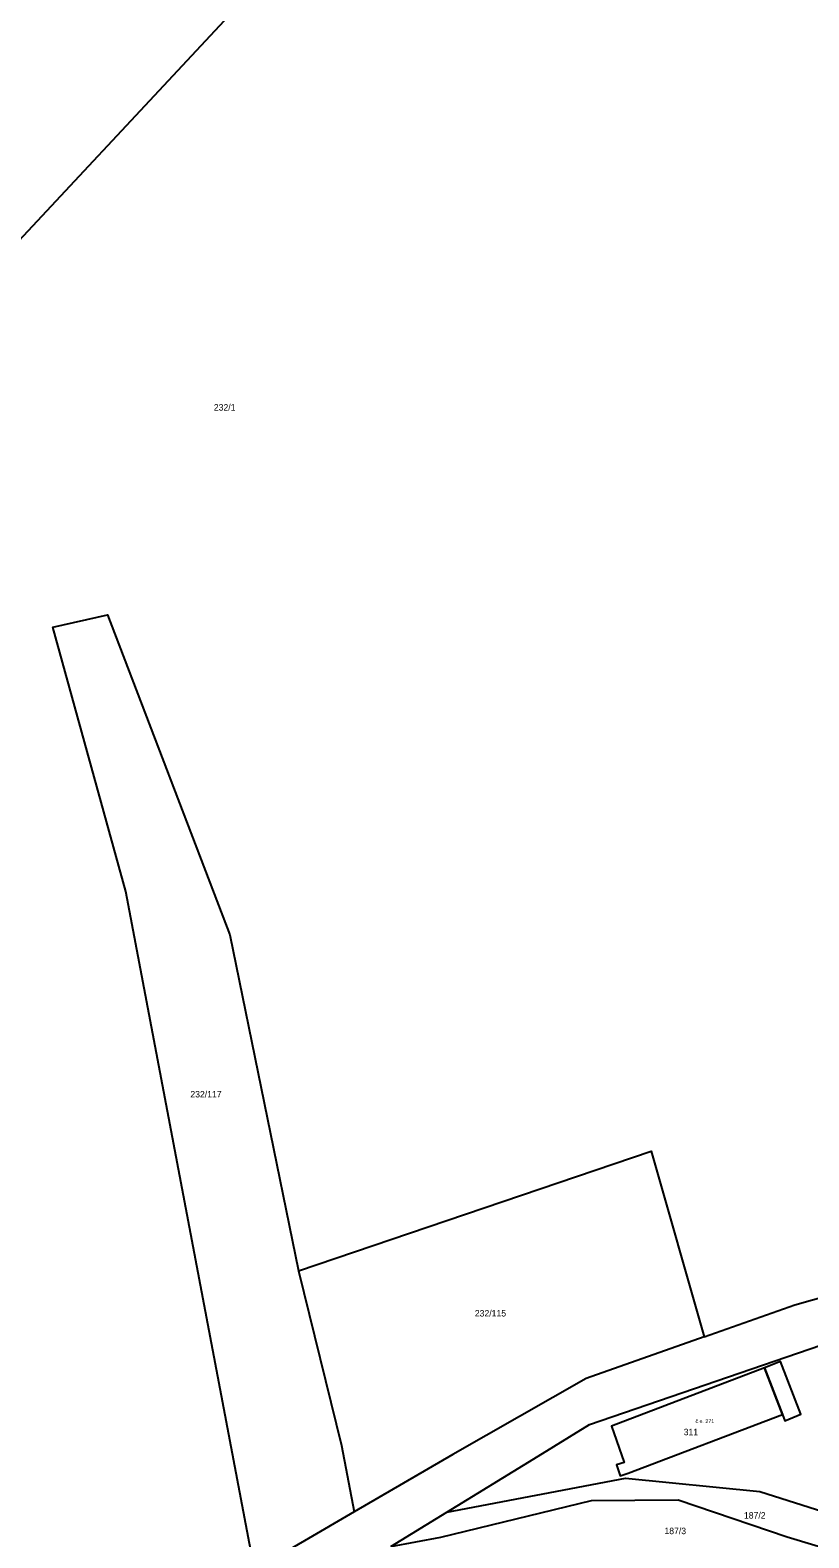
# Model space of a CAD drawing. Extents: x -887272 to -877616, y -1026687 to -1019819.
# Drawn here: x -882233.5 to -882028.8, y -1024011.9 to -1023615.5 of the extents above; entities that cross this region are included whole.
import ezdxf

# ---------------------------------------------------------------- set-up
doc = ezdxf.new("R2010")
doc.units = 0
for name, color, linetype in [('Definiční body', 7, 'Continuous'), ('Hranice parcel', 7, 'Continuous'), ('Parcelní čísla', 7, 'Continuous'), ('Polygon budovy', 7, 'Continuous'), ('Vnitřní kresba', 7, 'Continuous')]:
    doc.layers.add(name, color=color, linetype=linetype)

msp = doc.modelspace()

# ---------------------------------------------------------------- linework, layer by layer
at = {"layer": 'Hranice parcel'}
for p, q in [((-882123.98, -1024005.14), (-882101.11, -1023991.13)), ((-882138.72, -1024014.17), (-882123.98, -1024005.14))]:
    msp.add_line(p, q, dxfattribs=at)
for points in [[(-882058.02, -1023479.44), (-882103.84, -1023528.65), (-882178.79, -1023609.12), (-882251.38, -1023686.73), (-882326.67, -1023766.9), (-882416, -1023862), (-882806.28, -1023803.54), (-882785.58, -1023775.53)], [(-882174.49, -1024020.26), (-882208.33, -1023841.98), (-882227.5, -1023772.45), (-882213.17, -1023769.2), (-882180.99, -1023853.37), (-882162.93, -1023941.67)], [(-882162.93, -1023941.67), (-882070.28, -1023910.2), (-882056.31, -1023959.06)], [(-882162.93, -1023941.67), (-882151.68, -1023987.61), (-882148.29, -1024005.05)], [(-882056.31, -1023959.06), (-882032.46, -1023950.59), (-881999.39, -1023941.22)], [(-882101.11, -1023991.13), (-882086.42, -1023982.08), (-882025.64, -1023961.24), (-882008.61, -1023955.57)], [(-882056.31, -1023959.06), (-882087.32, -1023970), (-882122.36, -1023989.99), (-882148.29, -1024005.05)], [(-882078.4, -1023995.56), (-882076.31, -1023994.87), (-882035.71, -1023979.43), (-882035.06, -1023981.12), (-882030.88, -1023979.36), (-882036.2, -1023965.56), (-882040.44, -1023967.18), (-882080.7, -1023982.54), (-882077.3, -1023992.09), (-882079.32, -1023992.72), (-882078.4, -1023995.56)], [(-882123.98, -1024005.14), (-882077.02, -1023996.18), (-882041.7, -1023999.68), (-882017.67, -1024007.34), (-881998.04, -1024010.02)], [(-882138.72, -1024014.17), (-882125.55, -1024011.67), (-882085.96, -1024002.08), (-882063.17, -1024001.87), (-882034.49, -1024011.62), (-882004.55, -1024020.66), (-881996.26, -1024020.9)], [(-882148.29, -1024005.05), (-882161.34, -1024012.72), (-882174.49, -1024020.26)]]:
    msp.add_lwpolyline(points, dxfattribs=at)
at = {"layer": 'Polygon budovy'}
msp.add_lwpolyline([(-882080.7, -1023982.54), (-882077.3, -1023992.09), (-882079.32, -1023992.72), (-882078.4, -1023995.56), (-882076.31, -1023994.87), (-882035.71, -1023979.43), (-882040.44, -1023967.18)], close=True, dxfattribs=at)
at = {"layer": 'Vnitřní kresba'}
msp.add_line((-882040.44, -1023967.18), (-882035.71, -1023979.43), dxfattribs=at)

# ---------------------------------------------------------------- texts
at = {"layer": 'Definiční body'}
msp.add_text('č.e. 271', height=1, dxfattribs=at).set_placement((-882058.59, -1023981.73))
at = {"layer": 'Parcelní čísla'}
for s, p in [('232/1', (-882185.21, -1023715.54)), ('232/117', (-882191.38, -1023896.11)), ('232/115', (-882116.6, -1023953.7)), ('311', (-882061.69, -1023984.92)), ('187/2', (-882045.85, -1024006.83)), ('187/3', (-882066.75, -1024010.92))]:
    msp.add_text(s, height=1.7, dxfattribs=at).set_placement(p)

doc.saveas('drawing.dxf')
